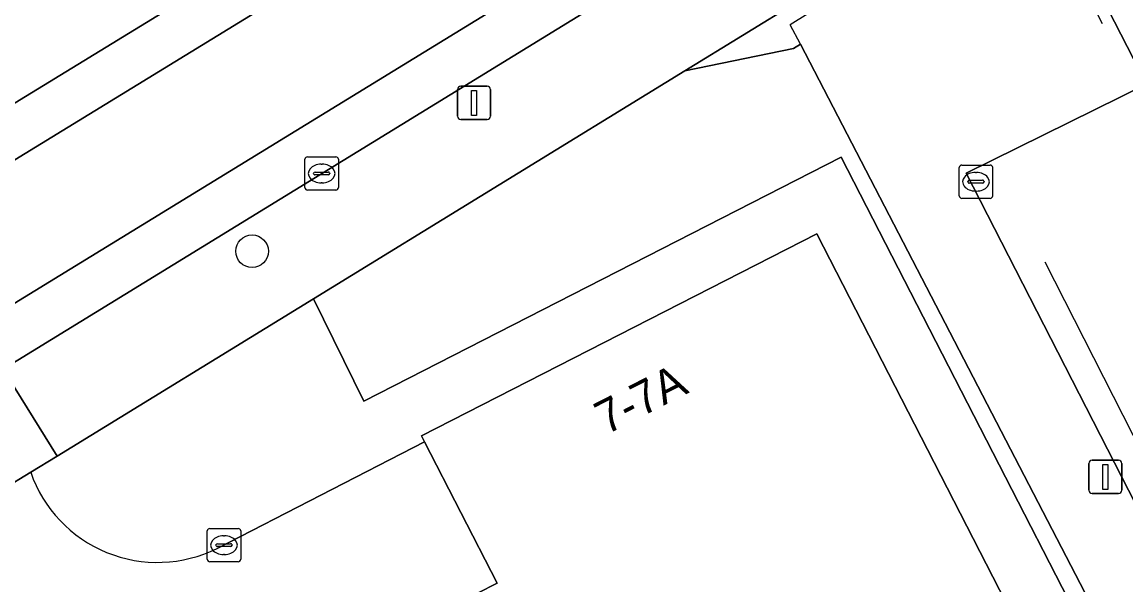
# Model space of a CAD drawing. Extents: x 158455 to 159797, y 387218 to 388672.
# Drawn here: x 159099.92 to 159133.04, y 387510.05 to 387526.95 of the extents above; entities that cross this region are included whole.
import ezdxf

# ---------------------------------------------------------------- set-up
doc = ezdxf.new("R2010")
doc.units = 0
for name, color, linetype in [('IMGEO_Boom', 7, 'Continuous'), ('IMGEO_Erf', 7, 'Continuous'), ('IMGEO_Groenvoorziening', 7, 'Continuous'), ('IMGEO_Hek', 7, 'Continuous'), ('IMGEO_Kolk', 7, 'Continuous'), ('IMGEO_Lichtmast', 7, 'Continuous'), ('IMGEO_Pand', 7, 'Continuous'), ('IMGEO_Pand_nummerreeks', 7, 'Continuous'), ('IMGEO_Parkeervlak_open', 7, 'Continuous'), ('IMGEO_Rijbaan_lokaal_gesloten', 7, 'Continuous'), ('IMGEO_Voetpad_open', 7, 'Continuous')]:
    doc.layers.add(name, color=color, linetype=linetype)

msp = doc.modelspace()

# ---------------------------------------------------------------- linework, layer by layer
at = {"layer": 'IMGEO_Boom'}
msp.add_circle((159106.825, 387520.071), 0.489, dxfattribs=at)
at = {"layer": 'IMGEO_Erf'}
for points in [[(159113.583, 387509.807), (159114.173, 387510.11), (159112, 387514.346), (159105.773, 387511.152)], [(159100.182, 387513.436), (159095.93, 387510.833)]]:
    msp.add_lwpolyline(points, dxfattribs=at)
msp.add_arc((159103.981, 387514.751), 4.02, 199.0878, 296.4708, dxfattribs=at)
at = {"layer": 'IMGEO_Groenvoorziening'}
msp.add_lwpolyline([(159169.155, 387437.467), (159170.983, 387438.519), (159167.872, 387444.948), (159167.45, 387445.82), (159128.252, 387522.415), (159133.657, 387525.085), (159130.188, 387531.865), (159119.81, 387525.491), (159123.068, 387526.158), (159123.276, 387526.283), (159161.61, 387452.318), (159160.9, 387451.958), (159161.259, 387451.075), (159159.251, 387450.057), (159159.513, 387449.265)], dxfattribs=at)
msp.add_lwpolyline([(159108.669, 387518.647), (159110.177, 387515.573), (159124.499, 387522.899), (159136.249, 387500), (159160.9, 387451.958), (159161.61, 387452.318), (159123.276, 387526.283), (159123.068, 387526.158), (159119.81, 387525.491)], close=True, dxfattribs=at)
at = {"layer": 'IMGEO_Hek'}
for points in [[(159132.337, 387526.894), (159130.066, 387531.301), (159122.972, 387526.87)], [(159123.276, 387526.283), (159122.972, 387526.87)], [(159119.81, 387525.491), (159123.068, 387526.158), (159123.276, 387526.283)], [(159161.61, 387452.318), (159123.276, 387526.283)], [(159130.604, 387519.749), (159142.62, 387496.129)]]:
    msp.add_lwpolyline(points, dxfattribs=at)
at = {"layer": 'IMGEO_Kolk'}
for p, q in [((159108.411, 387521.98), (159108.411, 387522.832)), ((159108.486, 387522.906), (159109.338, 387522.906)), ((159109.412, 387522.832), (159109.412, 387521.98)), ((159108.67, 387522.4), (159108.67, 387522.412)), ((159109.108, 387522.363), (159108.71, 387522.363)), ((159108.713, 387522.449), (159109.111, 387522.449)), ((159108.899, 387522.686), (159108.924, 387522.686)), ((159109.154, 387522.412), (159109.154, 387522.4)), ((159128.041, 387521.732), (159128.041, 387522.584)), ((159128.116, 387522.658), (159128.968, 387522.658)), ((159128.529, 387522.438), (159128.554, 387522.438)), ((159129.042, 387522.584), (159129.042, 387521.732)), ((159108.922, 387522.126), (159108.897, 387522.126)), ((159128.3, 387522.152), (159128.3, 387522.164)), ((159128.738, 387522.115), (159128.34, 387522.115)), ((159128.343, 387522.201), (159128.741, 387522.201)), ((159128.784, 387522.164), (159128.784, 387522.152)), ((159109.338, 387521.906), (159108.486, 387521.906)), ((159128.552, 387521.878), (159128.527, 387521.878)), ((159128.968, 387521.658), (159128.116, 387521.658)), ((159105.481, 387510.823), (159105.481, 387511.675)), ((159105.556, 387511.749), (159106.408, 387511.749)), ((159105.969, 387511.529), (159105.994, 387511.529)), ((159106.482, 387511.675), (159106.482, 387510.823)), ((159105.74, 387511.243), (159105.74, 387511.255)), ((159106.178, 387511.206), (159105.78, 387511.206)), ((159105.783, 387511.292), (159106.181, 387511.292)), ((159106.224, 387511.255), (159106.224, 387511.243)), ((159105.992, 387510.969), (159105.967, 387510.969)), ((159106.408, 387510.749), (159105.556, 387510.749))]:
    msp.add_line(p, q, dxfattribs=at)
for points in [[(159108.411, 387521.98), (159108.411, 387522.832)], [(159108.486, 387522.906), (159109.338, 387522.906)], [(159109.412, 387522.832), (159109.412, 387521.98)], [(159128.041, 387521.732), (159128.041, 387522.584)], [(159128.116, 387522.658), (159128.968, 387522.658)], [(159129.042, 387522.584), (159129.042, 387521.732)], [(159109.338, 387521.906), (159108.486, 387521.906)], [(159128.968, 387521.658), (159128.116, 387521.658)], [(159105.481, 387510.823), (159105.481, 387511.675)], [(159105.556, 387511.749), (159106.408, 387511.749)], [(159106.482, 387511.675), (159106.482, 387510.823)], [(159106.408, 387510.749), (159105.556, 387510.749)]]:
    msp.add_lwpolyline(points, dxfattribs=at)
for centre, radius, start, end in [((159108.488, 387522.83), 0.0765, 91.552, 178.448), ((159108.488, 387522.83), 0.0765, 91.552, 178.448), ((159109.336, 387522.83), 0.0765, 1.552, 88.448), ((159109.336, 387522.83), 0.0765, 1.552, 88.448), ((159108.71, 387522.409), 0.0403, 85.8775, 175.7526), ((159108.707, 387522.399), 0.0366, 178.938, 274.7102), ((159109.111, 387522.406), 0.043, 264.8664, 352.4533), ((159109.115, 387522.411), 0.0386, 1.7309, 96.639), ((159128.118, 387522.582), 0.0765, 91.552, 178.448), ((159128.118, 387522.582), 0.0765, 91.552, 178.448), ((159128.966, 387522.582), 0.0765, 1.552, 88.448), ((159128.966, 387522.582), 0.0765, 1.552, 88.448), ((159128.34, 387522.161), 0.0403, 85.8775, 175.7526), ((159128.337, 387522.151), 0.0366, 178.938, 274.7102), ((159128.741, 387522.158), 0.043, 264.8664, 352.4533), ((159128.745, 387522.163), 0.0386, 1.7309, 96.639), ((159108.488, 387521.982), 0.0765, 181.552, 268.448), ((159108.488, 387521.982), 0.0765, 181.552, 268.448), ((159109.336, 387521.982), 0.0765, 271.552, 358.448), ((159109.336, 387521.982), 0.0765, 271.552, 358.448), ((159128.118, 387521.734), 0.0765, 181.552, 268.448), ((159128.118, 387521.734), 0.0765, 181.552, 268.448), ((159128.966, 387521.734), 0.0765, 271.552, 358.448), ((159128.966, 387521.734), 0.0765, 271.552, 358.448), ((159105.558, 387511.673), 0.0765, 91.552, 178.448), ((159105.558, 387511.673), 0.0765, 91.552, 178.448), ((159106.406, 387511.673), 0.0765, 1.552, 88.448), ((159106.406, 387511.673), 0.0765, 1.552, 88.448), ((159105.78, 387511.252), 0.0403, 85.8775, 175.7526), ((159105.777, 387511.242), 0.0366, 178.938, 274.7102), ((159106.181, 387511.249), 0.043, 264.8664, 352.4533), ((159106.185, 387511.254), 0.0386, 1.7309, 96.639), ((159105.558, 387510.825), 0.0765, 181.552, 268.448), ((159105.558, 387510.825), 0.0765, 181.552, 268.448), ((159106.406, 387510.825), 0.0765, 271.552, 358.448), ((159106.406, 387510.825), 0.0765, 271.552, 358.448)]:
    msp.add_arc(centre, radius, start, end, dxfattribs=at)
for centre, major_axis, ratio, start_param, end_param in [((159108.898, 387522.406), (-0.387, 0.002), 0.722429, 4.712389, 7.853982), ((159108.923, 387522.406), (-0.39, 0.002), 0.717154, 1.570796, 4.712389), ((159128.528, 387522.158), (-0.387, 0.002), 0.722429, 4.712389, 7.853982), ((159128.553, 387522.158), (-0.39, 0.002), 0.717154, 1.570796, 4.712389), ((159105.968, 387511.249), (-0.387, 0.002), 0.722429, 4.712389, 7.853982), ((159105.993, 387511.249), (-0.39, 0.002), 0.717154, 1.570796, 4.712389)]:
    msp.add_ellipse(centre, major_axis=major_axis, ratio=ratio, start_param=start_param, end_param=end_param, dxfattribs=at)
at = {"layer": 'IMGEO_Lichtmast'}
for p, q in [((159113.086, 387525.025), (159113.876, 387525.025)), ((159113.876, 387525.025), (159113.086, 387525.025)), ((159112.986, 387524.125), (159112.986, 387524.925)), ((159112.986, 387524.925), (159112.986, 387524.125)), ((159113.976, 387524.925), (159113.976, 387524.125)), ((159113.976, 387524.125), (159113.976, 387524.925)), ((159113.876, 387524.025), (159113.086, 387524.025)), ((159113.086, 387524.025), (159113.876, 387524.025)), ((159132.028, 387513.796), (159132.818, 387513.796)), ((159132.818, 387513.796), (159132.028, 387513.796)), ((159131.928, 387512.896), (159131.928, 387513.696)), ((159131.928, 387513.696), (159131.928, 387512.896)), ((159132.918, 387513.696), (159132.918, 387512.896)), ((159132.918, 387512.896), (159132.918, 387513.696)), ((159132.818, 387512.796), (159132.028, 387512.796)), ((159132.028, 387512.796), (159132.818, 387512.796))]:
    msp.add_line(p, q, dxfattribs=at)
for points in [[(159113.406, 387524.9), (159113.556, 387524.9), (159113.556, 387524.15), (159113.406, 387524.15), (159113.406, 387524.9)], [(159132.348, 387513.671), (159132.498, 387513.671), (159132.498, 387512.921), (159132.348, 387512.921), (159132.348, 387513.671)]]:
    msp.add_lwpolyline(points, dxfattribs=at)
for centre, start, end in [((159113.086, 387524.925), 90, 180), ((159113.086, 387524.925), 90, 180), ((159113.876, 387524.925), 0, 90), ((159113.876, 387524.925), 360, 90), ((159113.086, 387524.125), 180, 270), ((159113.086, 387524.125), 180, 270), ((159113.876, 387524.125), 270, 0), ((159113.876, 387524.125), 270, 0), ((159132.028, 387513.696), 90, 180), ((159132.028, 387513.696), 90, 180), ((159132.818, 387513.696), 0, 90), ((159132.818, 387513.696), 360, 90), ((159132.028, 387512.896), 180, 270), ((159132.028, 387512.896), 180, 270), ((159132.818, 387512.896), 270, 0), ((159132.818, 387512.896), 270, 0)]:
    msp.add_arc(centre, 0.1, start, end, dxfattribs=at)
at = {"layer": 'IMGEO_Pand'}
msp.add_lwpolyline([(159156.811, 387449.824), (159158.181, 387450.55), (159160.08, 387451.556), (159147.747, 387475.562), (159147.042, 387475.201), (159134.325, 387500), (159123.765, 387520.592), (159111.908, 387514.526), (159112, 387514.346), (159114.173, 387510.11), (159113.583, 387509.807)], dxfattribs=at)
at = {"layer": 'IMGEO_Parkeervlak_open'}
msp.add_lwpolyline([(159027.513, 387481.181), (159026.877, 387482.18), (159024.963, 387481.026), (159023.269, 387479.962), (159018.035, 387476.998), (159017.182, 387476.601), (159018.053, 387474.867), (159023.896, 387478.124), (159121.481, 387537.858)], dxfattribs=at)
at = {"layer": 'IMGEO_Rijbaan_lokaal_gesloten'}
for points in [[(159133.229, 387549.041), (159131.804, 387548.467), (159132.872, 387546.133), (159133.561, 387544.061), (159133.59, 387542.706), (159133.317, 387541.303), (159132.756, 387539.948), (159131.877, 387538.704), (159130.75, 387537.685), (159126.453, 387534.93), (159019.808, 387469.507), (159020.676, 387468.281), (159024.359, 387470.558), (159047.885, 387485.004), (159051.33, 387487.098), (159060.651, 387492.816), (159093.351, 387512.877)], [(159019.808, 387469.507), (159126.453, 387534.93), (159130.75, 387537.685), (159131.877, 387538.704), (159132.756, 387539.948), (159133.317, 387541.303), (159133.59, 387542.706), (159133.561, 387544.061), (159132.872, 387546.133), (159131.804, 387548.467), (159128.209, 387547.02), (159128.678, 387545.688), (159128.83, 387544.305), (159128.794, 387543.65), (159128.698, 387543.022), (159128.387, 387541.954), (159128.138, 387541.384), (159127.481, 387540.337), (159126.573, 387539.372), (159125.668, 387538.733), (159024.654, 387476.829)], [(159008.396, 387469.517), (159010.601, 387470.186), (159013.378, 387471.157), (159016.309, 387472.364), (159018.744, 387473.535), (159024.654, 387476.829), (159125.668, 387538.733), (159126.573, 387539.372), (159127.481, 387540.337), (159128.138, 387541.384), (159128.387, 387541.954), (159128.698, 387543.022), (159128.794, 387543.65), (159128.83, 387544.305), (159128.678, 387545.688), (159128.209, 387547.02), (159126.829, 387546.593), (159126.933, 387546.399)], [(159124.964, 387539.982), (159121.878, 387538.085), (159121.481, 387537.858), (159023.896, 387478.124), (159018.053, 387474.867)], [(159093.351, 387512.877), (159099.356, 387516.529), (159126.181, 387533.011), (159127.42, 387533.785)]]:
    msp.add_lwpolyline(points, dxfattribs=at)
at = {"layer": 'IMGEO_Voetpad_open'}
for points in [[(159155.38, 387548.834), (159139.324, 387544.489), (159139.992, 387543.233), (159139.101, 387542.753), (159141.541, 387537.995), (159130.188, 387531.865), (159133.657, 387525.085), (159128.252, 387522.415), (159167.45, 387445.82), (159170.383, 387447.329), (159189.892, 387457.367), (159192.307, 387458.609), (159178.552, 387485.484), (159152.431, 387536.583), (159152.117, 387537.197), (159167.529, 387545.053), (159167.842, 387544.44), (159181.83, 387517.056)], [(159128.076, 387532.699), (159127.42, 387533.785), (159126.181, 387533.011), (159099.356, 387516.529), (159100.98, 387513.924), (159108.669, 387518.647), (159119.81, 387525.491), (159130.188, 387531.865), (159141.541, 387537.995), (159139.101, 387542.753)], [(159105.773, 387511.152), (159112, 387514.346), (159111.908, 387514.526), (159123.765, 387520.592), (159134.325, 387500), (159147.042, 387475.201), (159147.747, 387475.562), (159160.08, 387451.556), (159160.9, 387451.958), (159136.249, 387500), (159124.499, 387522.899), (159110.177, 387515.573), (159108.669, 387518.647), (159100.98, 387513.924), (159100.182, 387513.436)]]:
    msp.add_lwpolyline(points, dxfattribs=at)
msp.add_lwpolyline([(159100.98, 387513.924), (159099.356, 387516.529), (159093.351, 387512.877), (159094.978, 387510.25), (159095.93, 387510.833), (159100.182, 387513.436)], close=True, dxfattribs=at)
msp.add_arc((159103.981, 387514.751), 4.02, 199.0878, 296.4708, dxfattribs=at)

# ---------------------------------------------------------------- texts
at = {"layer": 'IMGEO_Pand_nummerreeks'}
msp.add_text('7-7A', height=1, rotation=27.0952, dxfattribs=at).set_placement((159117.446, 387514.551))

doc.saveas('drawing.dxf')
